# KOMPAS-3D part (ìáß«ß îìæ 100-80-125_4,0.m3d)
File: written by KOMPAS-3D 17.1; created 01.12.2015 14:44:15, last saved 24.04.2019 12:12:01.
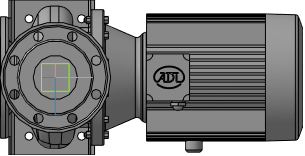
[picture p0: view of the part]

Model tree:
1. Операция без истории:2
